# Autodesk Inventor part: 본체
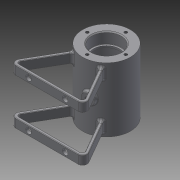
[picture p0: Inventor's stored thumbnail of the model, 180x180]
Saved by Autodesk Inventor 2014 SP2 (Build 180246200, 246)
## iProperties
Created: 2016-03
Part Number: 본체
Material: 일반
Document SubType Name: Modeling
Designer: 이도윤
Density: 1 g/cm^3
Appearance: 기본값
Mass: 78.7283 g
Surface Area: 333.838 cm^2
Volume: 78.7283 cm^3
Author: 이도윤
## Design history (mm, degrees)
sketch "스케치1"
  geometry: C1 r 26 at (0, 65); 1 further point
  constraints: 1 centre point, 1 vertical alignment
  dimensions: "d1" = 52 diameter of C1; "d2" = 65 distance of point (0, 0) C1.centre
extrude "돌출1" new body sketch "스케치1" distance "d3" = 70; taper "d4" = 0 deg
sketch "스케치2"
  geometry: C1 r 26 at (0, 0) reference; C2 r 16 at (0, 0); 1 further point
  constraints: 1 centre point, 1 coincident
  dimensions: "d5" = 32 diameter of C2
extrude "돌출2" cut sketch "스케치2" distance "d6" = 12; taper "d7" = 0 deg
sketch "스케치4"
  geometry: C1 r 16 at (0, 0) reference; C2 r 14 at (0, 0); 1 further point
  constraints: 1 centre point, 1 coincident
  dimensions: "d11" = 28 diameter of C2
extrude "돌출4" cut sketch "스케치4" distance "d12" = 2; taper "d13" = 0 deg
sketch "스케치5"
  geometry: C1 r 14 at (0, 0) reference; C2 r 21 at (0, 0); 1 further point
  constraints: 1 centre point, 1 coincident
  dimensions: "d14" = 42 diameter of C2
extrude "돌출5" cut sketch "스케치5" distance "d15" = 42; taper "d16" = 0 deg
sketch "스케치6"
  geometry: C1 r 26 at (0, 0) reference; C2 r 16 at (0, 0); 1 further point
  constraints: 1 centre point, 1 coincident
  dimensions: "d17" = 32 diameter of C2
extrude "돌출6" cut sketch "스케치6" distance "d18" = 12; taper "d19" = 0 deg
sketch "스케치7"
  geometry: C1 r 16 at (0, 0) reference; C2 r 14 at (0, 0); 1 further point
  constraints: 1 centre point, 1 coincident
  dimensions: "d20" = 28 diameter of C2
extrude "돌출7" cut sketch "스케치7" distance "d21" = 2; taper "d22" = 0 deg
node "작업 평면1"
sketch "스케치8"
  geometry: L1 (0, 63.034)-(0, -112.363); L2 (16.613, -20)-(42.594, -65); L3 (42.594, -65)-(-42.594, -65); L4 (-42.594, -65)-(-16.613, -20); L5 (-37.398, -62)-(-14.183, -21.791); L6 (-37.398, -62)-(37.398, -62); L7 (37.398, -62)-(14.183, -21.791); A1 r 26 centre (0, 0) between (16.613, -20) and (-16.613, -20) reference; A2 r 26 centre (0, 0) between (-16.613, -20) and (-14.183, -21.791); A3 r 26 centre (0, 0) between (0, -26) and (16.613, -20); 2 further points
  constraints: 14 end point, 7 point on circle, 3 parallel, 2 centre point, 2 coincident, 2 point on line, 1 midpoint, 1 perpendicular, 1 vertical, 1 vertical alignment
  dimensions: "d24" = 30 deg angle of L1 L2; "d25" = 30 deg angle of L1 L4; "d26" = 45 distance from line of L3 L2.start; "d27" = 3 distance between parallel lines of L4 L5; "d28" = 3 distance between parallel lines of L3 L6; "d29" = 3 distance between parallel lines of L2 L7
extrude "돌출8" join sketch "스케치8" distance "d32" = 10; taper "d33" = 0 deg
node "작업 평면2"
sketch "스케치9"
  geometry: C1 r 26 at (0, 0) reference; A1 r 21 centre (0, 0) between (0, 21) and (21, 0); 3 further points
  constraints: 4 point on circle, 1 centre point, 1 coincident
  dimensions: "d35" = 42 diameter of A1; "d36" = 42 distance of point (0, -21) A1.start; "d37" = 42 distance of A1.end point (-21, 0); "d38" = 21 horizontal distance of point (-21, 0) A1.start; "d39" = 21 horizontal distance of point (0, -21) point (-21, 0)
hole "구멍1" sketch "스케치9" at (0, 21), (21, 0), (0, -21), (-21, 0) diameter "d40" = 3.242; stored, may be unused: countersink angle "d44" = 90 deg, drill point angle "d46" = 118 deg; dims "d41" = 8, "d42" = 4, "d43" = 2, "d45" = 10
node "작업 평면4"
sketch "스케치10"
  geometry: L1 (26, 70)-(-26, 70) reference; L2 (26, 0)-(26, 70) reference; L3 (-26, 0)-(26, 0) reference; L4 (16.613, 5)-(16.613, 15) reference; L5 (16.613, 15)-(14.183, 15) reference; L6 (14.183, 15)-(14.183, 5) reference; L7 (14.183, 5)-(16.613, 5) reference; L8 (-16.613, 15)-(-16.613, 5) reference; L9 (-16.613, 5)-(-14.183, 5) reference; L10 (-14.183, 5)-(-14.183, 15) reference; L11 (-14.183, 15)-(-16.613, 15) reference; L12 (16.613, 55)-(16.613, 65) reference; L13 (16.613, 65)-(14.183, 65) reference; L14 (14.183, 65)-(14.183, 55) reference; L15 (14.183, 55)-(16.613, 55) reference; L16 (-16.613, 65)-(-16.613, 55) reference; L17 (-16.613, 55)-(-14.183, 55) reference; L18 (-14.183, 55)-(-14.183, 65) reference; L19 (-14.183, 65)-(-16.613, 65) reference; L20 (26, 70)-(-26, 70) reference; L21 (-26, 0)-(26, 0) reference; L22 (-26, 0)-(-26, 70) reference; C1 r 5 at (0, 35); 2 further points
  constraints: 1 centre point, 1 coincident
  dimensions: "d49" = 10 diameter of C1
extrude "돌출9" join sketch "스케치10" stored distance "d50" = 10; taper "d51" = 0 deg
sketch "스케치11"
  geometry: L1 (0, 42.85)-(0, -85.589); L2 (0, 0)-(24.51, -91.474); L3 (7.506, -28.012)-(13.301, -26.459); L4 (13.301, -26.459)-(12.343, -22.883); A1 r 26 centre (0, 0) between (6.729, -25.114) and (12.343, -22.883); 1 further point
  constraints: 8 end point, 2 perpendicular, 2 point on circle, 2 point on line, 1 centre point, 1 coincident, 1 vertical, 3 other
  dimensions: "d52" = 15 deg angle of L1 L2; "d53" = 6 distance of L3.start L3.end; "d54" = 29 distance of L3.start L2.start
revolve "회전1" sketch "스케치11" stored, may be unused: angle "d55" = 90 deg
sketch "스케치12"
  geometry: C1 r 5 at (0, 0) reference; 2 further points
  constraints: 1 coincident
hole "구멍2" sketch "스케치12" at (0, 0) diameter "d56" = 5.188; stored, may be unused: countersink angle "d60" = 90 deg, drill point angle "d62" = 0 deg; dims "d57" = 9, "d58" = 4, "d59" = 2, "d61" = 9
sketch "스케치13"
  geometry: C1 r 6 at (0, 0) reference; 2 further points
  constraints: 1 coincident
hole "구멍3" sketch "스케치13" at (0, 0) diameter "d63" = 5.188; stored, may be unused: countersink angle "d67" = 90 deg, drill point angle "d69" = 0 deg; dims "d64" = 9, "d65" = 4, "d66" = 2, "d68" = 9
sketch "스케치14"
  geometry: L1 (0, 10)-(74.796, 10) reference; L2 (0, 0)-(0, 10) reference; L3 (37.398, 78.286)-(37.398, -37.071); C1 r 3 at (17.398, 5); C2 r 3 at (57.398, 5); 1 further point
  constraints: 2 centre point, 2 end point, 1 parallel
  dimensions: "d70" = 6 diameter of C1; "d71" = 6 diameter of C2; "d72" = 40 distance of C1.centre C2.centre; "d73" = 20 horizontal distance of point (37.398, 65) C1.centre; "d74" = 5 distance from line of L1 C1.centre; "d75" = 5 distance from line of L1 C2.centre
extrude "돌출10" cut sketch "스케치14" stored distance "d76" = 10; taper "d77" = 0 deg
fillet "모깎기2" dims "d79" = 3
fillet "모깎기3" dims "d80" = 0.3
chamfer "모따기1" distance "d81" = 1; stored, may be unused: second distance "d82" = 2, angle "d83" = 45 deg
fillet "모깎기4" dims "d84" = 2
fillet "모깎기5" dims "d85" = 2
fillet "모깎기6" dims "d86" = 5
fillet "모깎기7" dims "d87" = 5
fillet "모깎기8" dims "d88" = 2.5
fillet "모깎기10" dims "d90" = 0.5
fillet "모깎기11" dims "d91" = 0.5
node "작업 평면7"
sketch "스케치16"
  geometry: L1 (19.407, 14.066)-(19.407, 55.934); L2 (19.407, 55.934)-(-19.407, 55.934); L3 (-19.407, 55.934)-(-19.407, 14.066); L4 (-19.407, 14.066)-(19.407, 14.066); L5 (-29, 30)-(-29, 40) reference; L6 (-26, 0)-(26, 0) reference; L7 (-26, 0)-(-26, 70) reference; 3 further points
  constraints: 2 midpoint, 2 other
  dimensions: "d92" = 26 distance from line of L7 point (0, 14.066); "d93" = 35 distance from line of L6 point (19.407, 35)
feature "엠보싱1" sketch "스케치16" dims "d1" = 52, "d2" = 65, "d94" = 0.5, "d95" = 0
fillet "모깎기12" dims "d96" = 3
node "솔리드1"
mirror "대칭1"
mirror "대칭2"
mirror "대칭3"
node "작업 평면3"
node "투영된 루프1"
node "작업 평면5"
node "작업 평면6"
other parameters: "d23" = -5, "d34" = -35, "d47" = 94
